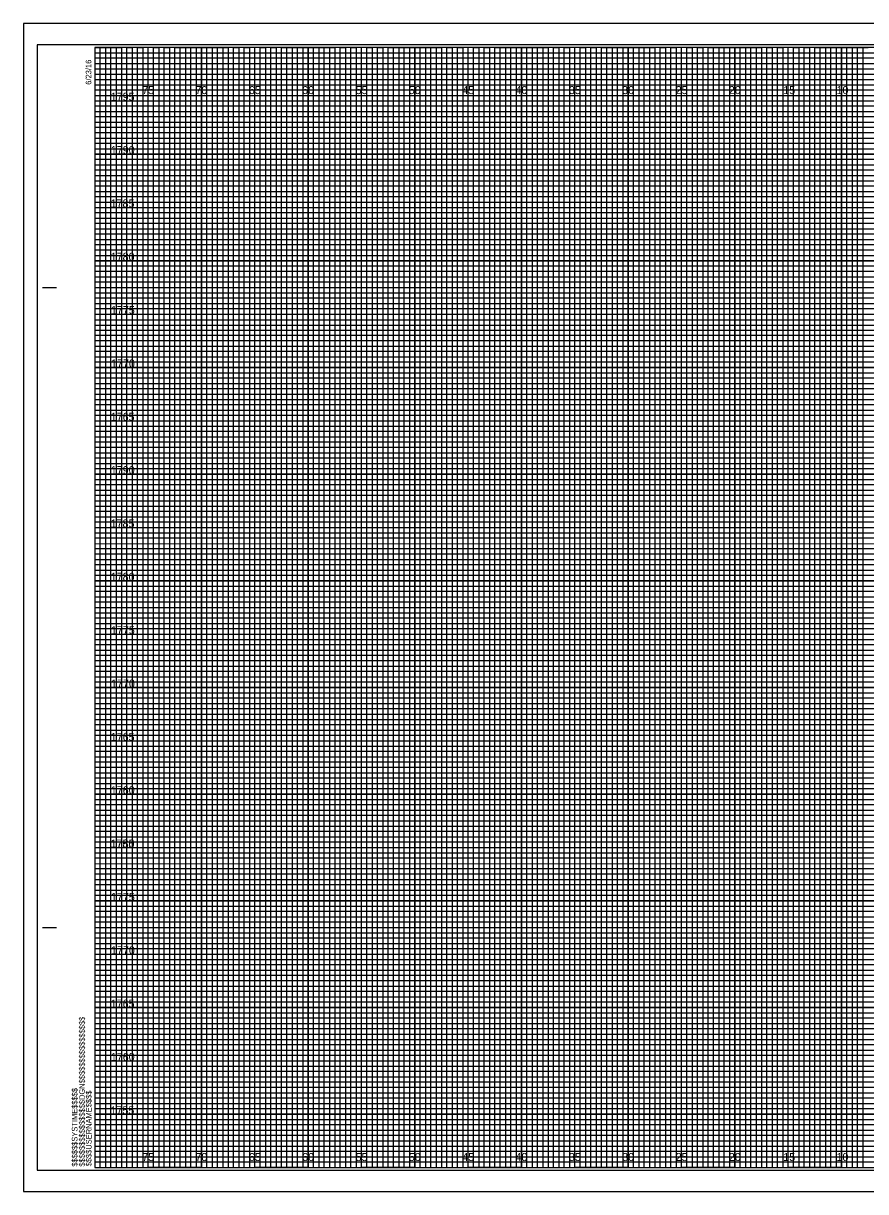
# Model space of a CAD drawing. Extents: x -7 to 162, y -2 to 217.
# Drawn here: x -6.7 to 72.2, y -2.3 to 107.3 of the extents above; entities that cross this region are included whole.
import ezdxf

# ---------------------------------------------------------------- set-up
doc = ezdxf.new("R2010")
doc.units = 0
for name, color, linetype in [('Raster_Level_0', 7, 'Continuous'), ('Scratch_Level_3', 7, 'Continuous'), ('Sheet Cross Section CELL', 7, 'Continuous'), ('Sheet Cross Section Grid Major CELL', 7, 'Continuous'), ('Sheet Cross Section Grid Middle CELL', 7, 'Continuous'), ('Sheet Cross Section Grid Minor 1 CELL', 7, 'Continuous'), ('Sheet Cross Section Grid Minor 2 CELL', 7, 'Continuous'), ('Sheet Cutting Line CELL', 7, 'Continuous'), ('Sheet DOT Grid CELL', 7, 'Continuous'), ('Sheet Plot Border Inside CELL', 7, 'Continuous'), ('Sheet Plot Border Outside CELL', 7, 'Continuous')]:
    doc.layers.add(name, color=color, linetype=linetype)

msp = doc.modelspace()

# ---------------------------------------------------------------- linework, layer by layer
at = {"layer": 'Sheet Cross Section CELL'}
for p, q in [((-4.9, 82.5), (-3.65, 82.5)), ((-4.85, 82.5), (-3.6, 82.5)), ((-4.9, 22.5), (-3.65, 22.5)), ((-4.85, 22.5), (-3.6, 22.5)), ((0, 0), (0, 0)), ((0, 0), (0, 0)), ((0, 0), (0, 0)), ((0, 0), (0, 0)), ((0, 0), (0, 0)), ((0, 0), (0, 0)), ((0, 0), (0, 0))]:
    msp.add_line(p, q, dxfattribs=at)
msp.add_lwpolyline([(160, 105), (0, 105), (0, 0), (160, 0)], close=True, dxfattribs=at)
at = {"layer": 'Sheet Cross Section Grid Major CELL'}
for p, q in [((5, 105), (0, 105)), ((5, 0), (5, 105)), ((15, 105), (10, 105)), ((10, 105), (10, 0)), ((15, 0), (15, 105)), ((25, 105), (20, 105)), ((20, 105), (20, 0)), ((25, 0), (25, 105)), ((35, 105), (30, 105)), ((30, 105), (30, 0)), ((35, 0), (35, 105)), ((45, 105), (40, 105)), ((40, 105), (40, 0)), ((45, 0), (45, 105)), ((55, 105), (50, 105)), ((50, 105), (50, 0)), ((55, 0), (55, 105)), ((65, 105), (60, 105)), ((60, 105), (60, 0)), ((65, 0), (65, 105)), ((75, 105), (70, 105)), ((70, 105), (70, 0)), ((10, 0), (5, 0)), ((20, 0), (15, 0)), ((30, 0), (25, 0)), ((40, 0), (35, 0)), ((50, 0), (45, 0)), ((60, 0), (55, 0)), ((70, 0), (65, 0))]:
    msp.add_line(p, q, dxfattribs=at)
for points in [[(0, 100), (160, 100), (160, 95), (0, 95)], [(0, 90), (160, 90), (160, 85), (0, 85)], [(0, 80), (160, 80), (160, 75), (0, 75)], [(0, 70), (160, 70), (160, 65), (0, 65)], [(0, 60), (160, 60), (160, 55), (0, 55)], [(0, 50), (160, 50), (160, 45), (0, 45)], [(0, 40), (160, 40), (160, 35), (0, 35)], [(0, 30), (160, 30), (160, 25), (0, 25)], [(0, 20), (160, 20), (160, 15), (0, 15)], [(0, 10), (160, 10), (160, 5), (0, 5)]]:
    msp.add_lwpolyline(points, dxfattribs=at)
at = {"layer": 'Sheet Cross Section Grid Middle CELL'}
for points in [[(0, 105), (2.5, 105), (2.5, 0), (7.5, 0), (7.5, 105), (12.5, 105), (12.5, 0), (17.5, 0), (17.5, 105), (22.5, 105), (22.5, 0), (27.5, 0), (27.5, 105), (32.5, 105), (32.5, 0), (37.5, 0), (37.5, 105), (42.5, 105), (42.5, 0), (47.5, 0), (47.5, 105), (52.5, 105), (52.5, 0), (57.5, 0), (57.5, 105), (62.5, 105), (62.5, 0), (67.5, 0), (67.5, 105), (72.5, 105)], [(0, 102.5), (137.5, 102.5)], [(0, 92.5), (160, 92.5), (160, 97.5), (0, 97.5)], [(0, 82.5), (160, 82.5), (160, 87.5), (0, 87.5)], [(0, 72.5), (160, 72.5), (160, 77.5), (0, 77.5)], [(0, 62.5), (160, 62.5), (160, 67.5), (0, 67.5)], [(0, 52.5), (160, 52.5), (160, 57.5), (0, 57.5)], [(0, 42.5), (160, 42.5), (160, 47.5), (0, 47.5)], [(0, 32.5), (160, 32.5), (160, 37.5), (0, 37.5)], [(0, 22.5), (160, 22.5), (160, 27.5), (0, 27.5)], [(0, 12.5), (160, 12.5), (160, 17.5), (0, 17.5)], [(0, 2.5), (160, 2.5), (160, 7.5), (0, 7.5)]]:
    msp.add_lwpolyline(points, dxfattribs=at)
at = {"layer": 'Sheet Cross Section Grid Minor 1 CELL'}
for p, q in [((0, 104.5), (130, 104.5)), ((130, 103.99), (0, 103.99)), ((0, 103.99), (0, 103.5)), ((0, 103.5), (130, 103.5)), ((130, 102.95), (0, 102.95)), ((0, 102.95), (0, 102)), ((0, 102), (160, 102))]:
    msp.add_line(p, q, dxfattribs=at)
for points in [[(0, 101.5), (135, 101.5), (160, 101.5), (160, 101), (0, 101)], [(0, 100.5), (160, 100.5), (160, 99.5), (0, 99.5)], [(0, 99), (160, 99), (160, 98.5), (0, 98.49)], [(0, 98), (160, 98), (160, 97), (0, 97)], [(0, 96.5), (160, 96.5), (160, 96), (0, 96)], [(0, 95.5), (160, 95.5), (160, 94.5), (0, 94.5)], [(0, 94), (160, 94), (160, 93.5), (0, 93.5)], [(0, 93), (160, 93), (160, 92), (0, 92)], [(0, 91.5), (160, 91.5), (160, 91), (0, 91)], [(0, 90.5), (160, 90.5), (160, 89.5), (0, 89.5)], [(0, 89), (160, 89), (160, 88.5), (0, 88.5)], [(0, 88), (160, 88), (160, 86.98), (160, 86.5), (160, 86), (0, 86)], [(0, 87), (160, 87), (160, 86.5), (0, 86.5)], [(0, 85.5), (160, 85.5), (160, 84.5), (0, 84.52)], [(0, 84.52), (160, 84.5), (160, 84), (0, 84)], [(0, 83.5), (160, 83.5), (160, 83), (0, 83)], [(0, 82), (160, 82), (160, 81.5), (0, 81.5)], [(0, 81), (160, 81), (160, 80.5), (0, 80.5)], [(-0.04, 79.45), (160, 79.45), (160, 78.94), (-0.04, 78.94)], [(0, 78.5), (160, 78.5), (160, 78), (0, 78)], [(0, 77), (160, 77), (160, 76.5), (0, 76.5)], [(0, 76), (160, 76), (160, 75.5), (0, 75.5)], [(0, 74.5), (160, 74.5), (160, 74), (0, 74)], [(0, 73.5), (160, 73.5), (160, 73), (0, 73)], [(0, 72), (160, 72), (160, 71.5), (0, 71.5)], [(0, 71), (160, 71), (160, 70.5), (0, 70.5)], [(0, 69.5), (160, 69.5), (160, 68.99), (0, 69)], [(0, 68.5), (160, 68.5), (160, 68), (0, 68)], [(0, 67), (160, 67), (160, 66.5), (0, 66.5)], [(0, 66), (160, 66), (160, 65.5), (0, 65.5)], [(0, 64.5), (160, 64.5), (160, 64), (0, 64)], [(0, 63.5), (160, 63.5), (160, 63), (0, 63)], [(0, 62), (160, 62), (160, 61.5), (0, 61.5)], [(0, 61), (160, 61), (160, 60.5), (0, 60.5)], [(0, 59.5), (160, 59.5), (160, 59), (0, 59)], [(0, 58.5), (160.03, 58.45), (160, 58), (0, 58)], [(0, 57), (160, 57), (160, 56.5), (0, 56.5)], [(0, 56), (160, 56), (160, 55.5), (0, 55.5)], [(0, 54.5), (160, 54.5), (160, 54), (0, 54)], [(0, 53.5), (160, 53.5), (160, 53), (0, 53)], [(0, 52), (160, 52), (160, 51.5), (0, 51.5)], [(0, 51), (160, 51), (160, 50.5), (0, 50.5)], [(0, 49.5), (160, 49.5), (160, 49), (0, 49)], [(0, 48.5), (160, 48.5), (160, 48), (0, 48)], [(0, 47), (160, 47), (160, 46.5), (0, 46.5)], [(0, 46), (160, 46), (160, 45.5), (0, 45.5)], [(0, 44.5), (160, 44.5), (160, 44), (0, 44)], [(0, 43.5), (160, 43.5), (160, 43), (0, 43)], [(0, 42), (160, 42), (160, 41.5), (0, 41.5)], [(0, 41), (160, 41), (160, 40.5), (0, 40.5)], [(0, 39.5), (160, 39.5), (160, 38.99), (0, 39)], [(0, 38.5), (160, 38.5), (160, 38), (0, 38)], [(0, 37), (160, 37), (160, 36.5), (0, 36.5)], [(0, 36), (160, 36), (160, 35.5), (0, 35.5)], [(0, 34.5), (160, 34.5), (160, 34), (0, 34)], [(0, 33.5), (160, 33.5), (160, 33), (0, 33)], [(0, 32), (160, 32), (160, 31.5), (0, 31.5)], [(0, 31), (160, 31), (160, 30.5), (0, 30.5)], [(0, 29.5), (160, 29.5), (160, 29), (0, 29)], [(0, 28.5), (160.03, 28.46), (160, 28), (0, 28)], [(0, 27), (160, 27), (160, 26.5), (0, 26.5)], [(0, 26), (160, 26), (160, 25.5), (0, 25.5)], [(0, 24.5), (160, 24.5), (160, 24), (0, 24)], [(0, 23.5), (160, 23.5), (160, 23), (0, 23)], [(0, 22), (160, 22), (160, 21.5), (0, 21.5)], [(0, 21), (160, 21), (160, 20.5), (0, 20.5)], [(0, 19.5), (160, 19.5), (160, 19), (0, 19)], [(0, 18.5), (160, 18.5), (160, 18), (0, 18)], [(0, 17), (160, 17), (160, 16.5), (0, 16.5)], [(0, 16), (160, 16), (160, 15.5), (0, 15.5)], [(0, 14.5), (160, 14.5), (160, 14), (0, 14)], [(0, 13.5), (160, 13.5), (160, 13), (0, 13)], [(0, 12), (160, 12), (160, 11.5), (0, 11.5)], [(0, 11), (160, 11), (160, 10.5), (0, 10.5)], [(0, 9.5), (160, 9.5), (160, 9), (0, 9)], [(0, 8.5), (160, 8.5), (160, 8), (0, 8)], [(0, 7), (160, 7), (160, 6.5), (0, 6.5)], [(0, 6), (160, 6), (160, 5.5), (0, 5.5)], [(0, 4.5), (160, 4.5), (160, 4), (0, 4)], [(0, 3.5), (160, 3.5), (160, 3), (0, 3)], [(0, 2), (160, 2), (160, 1.5), (0, 1.5)], [(0, 1), (160, 1), (160, 0.5), (0, 0.5)]]:
    msp.add_lwpolyline(points, dxfattribs=at)
at = {"layer": 'Sheet Cross Section Grid Minor 2 CELL'}
for points in [[(0, 0), (0.5, 0), (0.5, 105), (1, 105), (1, 0)], [(1, 0), (1.5, 0), (1.5, 105), (2, 105), (2, 0)], [(2.5, 0), (3, 0), (3, 105), (3.5, 105), (3.5, 0)], [(3.5, 0), (4, 0), (4, 105), (4.5, 105), (4.5, 0)], [(5, 0), (5.5, 0), (5.5, 105), (6, 105), (6, 0)], [(6, 0), (6.5, 0), (6.5, 105), (7, 105), (7, 0)], [(7.5, 0), (8, 0), (8, 105), (8.5, 105), (8.5, 0)], [(8.5, 0), (9, 0), (9, 105), (9.5, 105), (9.5, 0)], [(10, 0), (10.5, 0), (10.5, 105), (11, 105), (11, 0)], [(11, 0), (11.5, 0), (11.5, 105), (12, 105), (12, 0)], [(12.5, 0), (13, 0), (13, 105), (13.5, 105), (13.5, 0)], [(13.5, 0), (14, 0), (14, 105), (14.5, 105), (14.5, 0)], [(15, 0), (15.5, 0), (15.5, 105), (16, 105), (16, 0)], [(16, 0), (16.5, 0), (16.5, 105), (17, 105), (17, 0)], [(17.5, 0), (18, 0), (18, 105), (18.5, 105), (18.5, 0)], [(18.5, 0), (19, 0), (19, 105), (19.5, 105), (19.5, 0)], [(20, 0), (20.5, 0), (20.5, 105), (21, 105), (21, 0)], [(21, 0), (21.5, 0), (21.5, 105), (22, 105), (22, 0)], [(22.5, 0), (23, 0), (23, 105), (23.5, 105), (23.5, 0)], [(23.5, 0), (24, 0), (24, 105), (24.5, 105), (24.5, 0)], [(25, 0), (25.5, 0), (25.5, 105), (26, 105), (26, 0)], [(26, 0), (26.5, 0), (26.5, 105), (27, 105), (27, 0)], [(27.5, 0), (28, 0), (28, 105), (28.5, 105), (28.5, 0)], [(28.5, 0), (29, 0), (29, 105), (29.5, 105), (29.5, 0)], [(30, 0), (30.5, 0), (30.5, 105), (31, 105), (31, 0)], [(31, 0), (31.5, 0), (31.5, 105), (32, 105), (32, 0)], [(32.5, 0), (33, 0), (33, 105), (33.5, 105), (33.5, 0)], [(33.5, 0), (34, 0), (34, 105), (34.5, 105), (34.5, 0)], [(35, 0), (35.5, 0), (35.5, 105), (36, 105), (36, 0)], [(36, 0), (36.5, 0), (36.5, 105), (37, 105), (37, 0)], [(37.5, 0), (38, 0), (38, 105), (38.5, 105), (38.5, 0)], [(38.5, 0), (39, 0), (39, 105), (39.5, 105), (39.5, 0)], [(40, 0), (40.5, 0), (40.5, 105), (41, 105), (41, 0)], [(41, 0), (41.5, 0), (41.5, 105), (42, 105), (42, 0)], [(42.5, 0), (43, 0), (43, 105), (43.5, 105), (43.5, 0)], [(43.5, 0), (44, 0), (44, 105), (44.5, 105), (44.5, 0)], [(45, 0), (45.5, 0), (45.5, 105), (46, 105), (46, 0)], [(46, 0), (46.5, 0), (46.5, 105), (47, 105), (47, 0)], [(47.5, 0), (48, 0), (48, 105), (48.5, 105), (48.5, 0)], [(48.5, 0), (49, 0), (49, 105), (49.5, 105), (49.5, 0)], [(50, 0), (50.5, 0), (50.5, 105), (51, 105), (51, 0)], [(51, 0), (51.5, 0), (51.5, 105), (52, 105), (52, 0)], [(52.5, 0), (53, 0), (53, 105), (53.5, 105), (53.5, 0)], [(53.5, 0), (54, 0), (54, 105), (54.5, 105), (54.5, 0)], [(55, 0), (55.5, 0), (55.5, 105), (56, 105), (56, 0)], [(56, 0), (56.5, 0), (56.5, 105), (57, 105), (57, 0)], [(57.5, 0), (58, 0), (58, 105), (58.5, 105), (58.5, 0)], [(58.5, 0), (59, 0), (59, 105), (59.5, 105), (59.5, 0)], [(60, 0), (60.5, 0), (60.5, 105), (61, 105), (61, 0)], [(61, 0), (61.5, 0), (61.5, 105), (62, 105), (62, 0)], [(62.5, 0), (63, 0), (63, 105), (63.5, 105), (63.5, 0)], [(63.5, 0), (64, 0), (64, 105), (64.5, 105), (64.5, 0)], [(65, 0), (65.5, 0), (65.5, 105), (66, 105), (66, 0)], [(66, 0), (66.5, 0), (66.5, 105), (67, 105), (67, 0)], [(67.5, 0), (68, 0), (68, 105), (68.5, 105), (68.5, 0)], [(68.5, 0), (69, 0), (69, 105), (69.5, 105), (69.5, 0)], [(70, 0), (70.5, 0), (70.5, 105), (71, 105), (71, 0)], [(71, 0), (71.5, 0), (71.5, 105), (72, 105), (72, 0)]]:
    msp.add_lwpolyline(points, dxfattribs=at)
at = {"layer": 'Sheet Cutting Line CELL'}
for p, q in [((161.65, 107.25), (-6.7, 107.25)), ((-6.7, 107.25), (-6.7, -2.25)), ((-6.7, -2.25), (161.65, -2.25))]:
    msp.add_line(p, q, dxfattribs=at)
at = {"layer": 'Sheet DOT Grid CELL'}
for p, q in [((5, 0), (5, 105)), ((10, 0), (10, 105)), ((15, 0), (15, 105)), ((20, 0), (20, 105)), ((25, 0), (25, 105)), ((30, 0), (30, 105)), ((35, 0), (35, 105)), ((40, 0), (40, 105)), ((45, 0), (45, 105)), ((50, 0), (50, 105)), ((55, 0), (55, 105)), ((60, 0), (60, 105)), ((65, 0), (65, 105)), ((70, 0), (70, 105)), ((0, 100), (160, 100)), ((0, 95), (160, 95)), ((0, 90), (160, 90)), ((0, 85), (160, 85)), ((0, 80), (160, 80)), ((0, 75), (160, 75)), ((0, 70), (160, 70)), ((0, 65), (160, 65)), ((0, 60), (160, 60)), ((0, 55), (160, 55)), ((0, 50), (160, 50)), ((0, 45), (160, 45)), ((0, 40), (160, 40)), ((0, 35), (160, 35)), ((0, 30), (160, 30)), ((0, 25), (160, 25)), ((0, 20), (160, 20)), ((0, 15), (160, 15)), ((0, 10), (160, 10)), ((0, 5), (160, 5))]:
    msp.add_line(p, q, dxfattribs=at)
at = {"layer": 'Sheet Plot Border Inside CELL'}
msp.add_lwpolyline([(-5.4, -0.25), (161.2, -0.25), (161.2, 105.25), (-5.4, 105.25)], close=True, dxfattribs=at)
at = {"layer": 'Sheet Plot Border Outside CELL'}
msp.add_lwpolyline([(-6.7, -2.25), (161.65, -2.25), (161.65, 107.25), (-6.7, 107.25)], close=True, dxfattribs=at)

# ---------------------------------------------------------------- texts
at = {"layer": 'Raster_Level_0'}
for s, p in [('75', (4.44, 100.62)), ('70', (9.43, 100.62)), ('65', (14.44, 100.62)), ('60', (19.43, 100.62)), ('55', (24.44, 100.62)), ('50', (29.43, 100.62)), ('45', (34.44, 100.62)), ('40', (39.43, 100.62)), ('35', (44.44, 100.62)), ('30', (49.43, 100.62)), ('25', (54.44, 100.62)), ('20', (59.43, 100.62)), ('15', (64.53, 100.62)), ('10', (69.52, 100.62)), ('75', (4.44, 0.62)), ('70', (9.43, 0.62)), ('65', (14.44, 0.62)), ('60', (19.43, 0.62)), ('55', (24.44, 0.62)), ('50', (29.43, 0.62)), ('45', (34.44, 0.62)), ('40', (39.43, 0.62)), ('35', (44.44, 0.62)), ('30', (49.43, 0.62)), ('25', (54.44, 0.62)), ('20', (59.43, 0.62)), ('15', (64.53, 0.62)), ('10', (69.52, 0.62))]:
    msp.add_text(s, height=0.75, dxfattribs=at).set_placement(p)
at = {"layer": 'Scratch_Level_3'}
for s, p in [('1795', (1.49, 100)), ('1790', (1.5, 95)), ('1785', (1.48, 90)), ('1780', (1.49, 85)), ('1775', (1.51, 80)), ('1770', (1.52, 75)), ('1765', (1.49, 70)), ('1790', (1.5, 65)), ('1785', (1.48, 60)), ('1780', (1.49, 55)), ('1775', (1.51, 50)), ('1770', (1.52, 45)), ('1765', (1.49, 40)), ('1760', (1.5, 35)), ('1755', (1.47, 30)), ('1780', (1.49, 30)), ('1775', (1.51, 25)), ('1770', (1.52, 20)), ('1765', (1.49, 15)), ('1760', (1.5, 10)), ('1755', (1.47, 5))]:
    msp.add_text(s, height=0.75, dxfattribs=at).set_placement(p)
at = {"layer": 'Sheet Cross Section CELL'}
for s, p in [('6/23/16', (-0.33, 101.5)), ('$$$$$$$$$$$$$$$$DGN$$$$$$$$$$$$$$$$', (-0.94, 0.09)), ('$$$$$$SYSTIME$$$$$', (-1.63, 0.09)), ('$$$$USERNAME$$$$', (-0.31, 0.12))]:
    msp.add_text(s, height=0.525, rotation=90, dxfattribs=at).set_placement(p)

doc.saveas('drawing.dxf')
